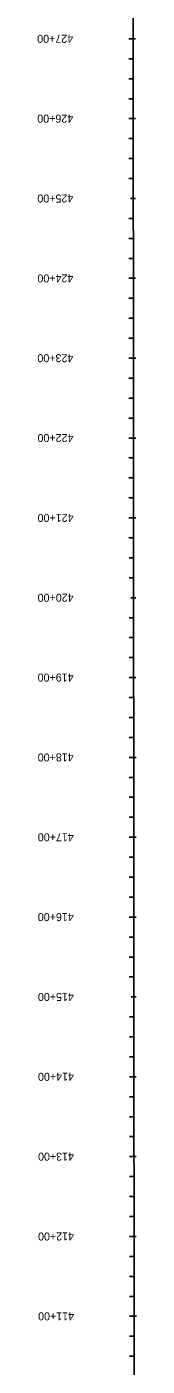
# Model space of a CAD drawing. Extents: x 23417911 to 23421158, y 6737892 to 6791804.
# Drawn here: x 23420712 to 23420836, y 6766535 to 6768213 of the extents above; entities that cross this region are included whole.
import ezdxf

# ---------------------------------------------------------------- set-up
doc = ezdxf.new("R2010")
doc.units = 0
for name, color, linetype in [('Alignment', 7, 'Continuous'), ('TextAlignmentLrg', 7, 'Continuous'), ('TextAlignmentSml', 7, 'Continuous')]:
    doc.layers.add(name, color=color, linetype=linetype)

msp = doc.modelspace()

# ---------------------------------------------------------------- linework, layer by layer
at = {"layer": 'Alignment'}
msp.add_line((23420834.6, 6764732), (23420829.5, 6771769.1), dxfattribs=at)
msp.add_line((23420834.6, 6764732), (23420829.5, 6771769.1), dxfattribs=at)
at = {"layer": 'TextAlignmentLrg'}
for p, q in [((23420832, 6768197.6), (23420826.6, 6768197.6)), ((23420832.1, 6768097.6), (23420826.7, 6768097.6)), ((23420829.1, 6767997.6), (23420835.3, 6767997.6)), ((23420832.3, 6767897.6), (23420826.8, 6767897.6)), ((23420832.3, 6767797.6), (23420826.9, 6767797.6)), ((23420832.4, 6767697.6), (23420826.9, 6767697.6)), ((23420832.5, 6767597.6), (23420827, 6767597.6)), ((23420829.5, 6767497.6), (23420835.6, 6767497.6)), ((23420832.6, 6767397.6), (23420827.2, 6767397.6)), ((23420832.7, 6767297.6), (23420827.2, 6767297.6)), ((23420832.8, 6767197.6), (23420827.3, 6767197.6)), ((23420832.8, 6767097.6), (23420827.4, 6767097.6)), ((23420829.9, 6766997.6), (23420836, 6766997.6)), ((23420833, 6766897.6), (23420827.5, 6766897.6)), ((23420833.1, 6766797.6), (23420827.6, 6766797.6)), ((23420833.1, 6766697.6), (23420827.7, 6766697.6)), ((23420833.2, 6766597.6), (23420827.7, 6766597.6))]:
    msp.add_line(p, q, dxfattribs=at)
at = {"layer": 'TextAlignmentSml'}
for p, q in [((23420829, 6768197.6), (23420835.1, 6768197.6)), ((23420832.1, 6768172.6), (23420826.6, 6768172.6)), ((23420832.1, 6768147.6), (23420826.6, 6768147.6)), ((23420832.1, 6768122.6), (23420826.6, 6768122.6)), ((23420829.1, 6768097.6), (23420835.2, 6768097.6)), ((23420832.1, 6768072.6), (23420826.7, 6768072.6)), ((23420832.2, 6768047.6), (23420826.7, 6768047.6)), ((23420832.2, 6768022.6), (23420826.7, 6768022.6)), ((23420829.1, 6767997.6), (23420835.3, 6767997.6)), ((23420832.2, 6767972.6), (23420826.7, 6767972.6)), ((23420832.2, 6767947.6), (23420826.8, 6767947.6)), ((23420832.2, 6767922.6), (23420826.8, 6767922.6)), ((23420829.2, 6767897.6), (23420835.3, 6767897.6)), ((23420832.3, 6767872.6), (23420826.8, 6767872.6)), ((23420832.3, 6767847.6), (23420826.8, 6767847.6)), ((23420832.3, 6767822.6), (23420826.9, 6767822.6)), ((23420829.3, 6767797.6), (23420835.4, 6767797.6)), ((23420832.4, 6767772.6), (23420826.9, 6767772.6)), ((23420832.4, 6767747.6), (23420826.9, 6767747.6)), ((23420832.4, 6767722.6), (23420826.9, 6767722.6)), ((23420829.3, 6767697.6), (23420835.5, 6767697.6)), ((23420832.4, 6767672.6), (23420827, 6767672.6)), ((23420832.4, 6767647.6), (23420827, 6767647.6)), ((23420832.5, 6767622.6), (23420827, 6767622.6)), ((23420829.4, 6767597.6), (23420835.5, 6767597.6)), ((23420832.5, 6767572.6), (23420827, 6767572.6)), ((23420832.5, 6767547.6), (23420827.1, 6767547.6)), ((23420832.5, 6767522.6), (23420827.1, 6767522.6)), ((23420829.5, 6767497.6), (23420835.6, 6767497.6)), ((23420832.6, 6767472.6), (23420827.1, 6767472.6)), ((23420832.6, 6767447.6), (23420827.1, 6767447.6)), ((23420832.6, 6767422.6), (23420827.1, 6767422.6)), ((23420829.6, 6767397.6), (23420835.7, 6767397.6)), ((23420832.6, 6767372.6), (23420827.2, 6767372.6)), ((23420832.7, 6767347.6), (23420827.2, 6767347.6)), ((23420832.7, 6767322.6), (23420827.2, 6767322.6)), ((23420829.6, 6767297.6), (23420835.8, 6767297.6)), ((23420832.7, 6767272.6), (23420827.3, 6767272.6)), ((23420832.7, 6767247.6), (23420827.3, 6767247.6)), ((23420832.8, 6767222.6), (23420827.3, 6767222.6)), ((23420829.7, 6767197.6), (23420835.8, 6767197.6)), ((23420832.8, 6767172.6), (23420827.3, 6767172.6)), ((23420832.8, 6767147.6), (23420827.3, 6767147.6)), ((23420832.8, 6767122.6), (23420827.4, 6767122.6)), ((23420829.8, 6767097.6), (23420835.9, 6767097.6)), ((23420832.9, 6767072.6), (23420827.4, 6767072.6)), ((23420832.9, 6767047.6), (23420827.4, 6767047.6)), ((23420832.9, 6767022.6), (23420827.4, 6767022.6)), ((23420829.9, 6766997.6), (23420836, 6766997.6)), ((23420832.9, 6766972.6), (23420827.5, 6766972.6)), ((23420833, 6766947.6), (23420827.5, 6766947.6)), ((23420833, 6766922.6), (23420827.5, 6766922.6)), ((23420829.9, 6766897.6), (23420836, 6766897.6)), ((23420833, 6766872.6), (23420827.5, 6766872.6)), ((23420833, 6766847.6), (23420827.6, 6766847.6)), ((23420833, 6766822.6), (23420827.6, 6766822.6)), ((23420830, 6766797.6), (23420836.1, 6766797.6)), ((23420833.1, 6766772.6), (23420827.6, 6766772.6)), ((23420833.1, 6766747.6), (23420827.6, 6766747.6)), ((23420833.1, 6766722.6), (23420827.7, 6766722.6)), ((23420830.1, 6766697.6), (23420836.2, 6766697.6)), ((23420833.2, 6766672.6), (23420827.7, 6766672.6)), ((23420833.2, 6766647.6), (23420827.7, 6766647.6)), ((23420833.2, 6766622.6), (23420827.7, 6766622.6)), ((23420830.1, 6766597.6), (23420836.3, 6766597.6)), ((23420833.2, 6766572.6), (23420827.8, 6766572.6)), ((23420833.2, 6766547.6), (23420827.8, 6766547.6))]:
    msp.add_line(p, q, dxfattribs=at)

# ---------------------------------------------------------------- texts
at = {"layer": 'TextAlignmentLrg'}
for s, p in [('425+00', (23420757.2, 6768002.6)), ('420+00', (23420757.6, 6767502.6)), ('415+00', (23420757.9, 6767002.6))]:
    msp.add_text(s, height=10.02, rotation=180.0416, dxfattribs=at).set_placement(p)
at = {"layer": 'TextAlignmentSml'}
for s, p in [('427+00', (23420757, 6768202.6)), ('426+00', (23420757.1, 6768102.6)), ('425+00', (23420757.2, 6768002.6)), ('424+00', (23420757.3, 6767902.6)), ('423+00', (23420757.3, 6767802.6)), ('422+00', (23420757.4, 6767702.6)), ('421+00', (23420757.5, 6767602.6)), ('420+00', (23420757.6, 6767502.6)), ('419+00', (23420757.6, 6767402.6)), ('418+00', (23420757.7, 6767302.6)), ('417+00', (23420757.8, 6767202.6)), ('416+00', (23420757.8, 6767102.6)), ('415+00', (23420757.9, 6767002.6)), ('414+00', (23420758, 6766902.6)), ('413+00', (23420758.1, 6766802.6)), ('412+00', (23420758.1, 6766702.6)), ('411+00', (23420758.2, 6766602.6))]:
    msp.add_text(s, height=10.02, rotation=180.0416, dxfattribs=at).set_placement(p)

doc.saveas('drawing.dxf')
